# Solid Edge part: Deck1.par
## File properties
Author: Marvin
Template: Iso Metric Part.par
Last saved by: m_hel
Revision: 23
Application: Solid Edge
Accuracy: 0,990
Username: Marvin
Material: Textured White
Face Style: White painted
Fill Style: ANSI36(Marble)
Virtual Style: ANSI36(Marble)
Grouping: Uncategorized
LibraryName: Custom Materials
Coef. of Thermal Exp: 0.0
Thermal Conductivity: 0.0
Specific Heat: 0.0
Modulus of Elasticity: 0.0
Poisson's Ratio: 0.0
Yield Stress: 0.0
Ultimate Stress: 0.0
Elongation: 0.0
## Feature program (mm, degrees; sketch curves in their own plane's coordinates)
sketch for "unnamed Protrusion 1" plane through (0, 0, 0) normal (0, 0, 1) x-axis (1, 0, 0)
  line (-1205, -2870) -> (-1205, -36.0362)
  arc centre (2833.7179, -36.0362) radius 4038.7179 from (-260.1195, 2560.0016) to (-1205, -36.0362) ccw
  line (0, 2870) -> (-260.1195, 2560.0016)
  line (0, -2870) -> (0, 2870)
  line (-1205, -2870) -> (0, -2870)
extrude "unnamed Protrusion 1" add finite 70 along +normal
mirror "unnamed Mirror 1" of "unnamed Protrusion 1" about plane through (0, 0, 0) normal (1, 0, 0)
extrude "unnamed Protrusion 2" add finite 70
sketch for "unnamed Cutout 1" plane through (0, 0, 0) normal (0, 0, 1) x-axis (1, 0, 0)
  line (-805, -1100) -> (805, -1100)
  line (805, -36.0362) -> (805, -1100)
  arc centre (-2833.7179, -36.0362) radius 3638.7179 from (725.5906, 720) to (805, -36.0362) cw
  line (-725.5906, 720) -> (725.5906, 720)
  arc centre (2833.7179, -36.0362) radius 3638.7179 from (-805, -36.0362) to (-725.5906, 720) cw
  line (-805, -1100) -> (-805, -36.0362)
extrude "unnamed Cutout 1" cut through along +normal
sketch for "ExtrudedCutout_2" plane through (0, 0, 70) normal (0, 0, 1) x-axis (0, -1, 0)
  arc centre (36.0362, 2833.7179) radius 3638.7179 from (-1120, -616.4775) to (-1670, -380.2685) cw
  line (-1670, -380.2685) -> (-1670, 380.2685)
  arc centre (36.0362, -2833.7179) radius 3638.7179 from (-1670, 380.2685) to (-1120, 616.4775) cw
  line (-1120, -616.4775) -> (-1120, 616.4775)
extrude "ExtrudedCutout_2" cut finite 50 along -normal
sketch for "ExtrudedCutout_3" plane through (0, 0, 70) normal (0, 0, 1) x-axis (0, -1, 0)
  line (1150, -500) -> (1600, -500)
  line (1600, -500) -> (1600, 500)
  line (1600, 500) -> (1150, 500)
  line (1150, 500) -> (1150, -500)
extrude "ExtrudedCutout_3" cut finite 50 along -normal
sketch for "unnamed Cutout 2" plane through (0, 0, 70) normal (0, 0, 1) x-axis (0, -1, 0)
extrude "unnamed Cutout 2" cut finite 50 along -normal
sketch for "ExtrudedCutout_5" plane through (0, 0, 70) normal (0, 0, 1) x-axis (0, -1, 0)
  line (2150, -250) -> (2150, 250)
  line (2150, 250) -> (1800, 250)
  line (1800, 250) -> (1800, -250)
  line (1800, -250) -> (2150, -250)
extrude "ExtrudedCutout_5" cut finite 50 along -normal
sketch for "unnamed Cutout 3" plane through (0, 0, 70) normal (0, 0, 1) x-axis (0, -1, 0)
  line (953.812, 885) -> (1000, 805)
  line (803.812, 885) -> (953.812, 885)
  line (757.624, 805) -> (803.812, 885)
extrude "unnamed Cutout 3" cut through along -normal
mirror "unnamed Mirror 2" of "unnamed Cutout 3" about plane through (0, 0, 0) normal (1, 0, 0)
extrude "unnamed Cutout 4" cut through
sketch used by "unnamed Cutout 5" plane through (0, 0, 0) normal (0, 0, -1) x-axis (1, 0, 0)
  line (-405.7962, 2870) -> (-300, 2270)
  line (-300, 2270) -> (300, 2270)
  line (300, 2270) -> (405.7962, 2870)
  dimension (linear) = 300
extrude "unnamed Cutout 5" cut through along -normal
sketch for "unnamed Cutout 6" #1 plane through (650, -2250, 20) normal (0, 0, 1) x-axis (0, 1, 0)
  line (430, 430) -> (430, 870)
  arc centre (420, 870) radius 10 from (420, 880) to (430, 870) cw
  line (420, 880) -> (130, 880)
  arc centre (130, 870) radius 10 from (130, 880) to (120, 870) ccw
  line (120, 870) -> (120, 430)
  arc centre (130, 430) radius 10 from (120, 430) to (130, 420) ccw
  line (130, 420) -> (420, 420)
  arc centre (420, 430) radius 10 from (420, 420) to (430, 430) ccw
sketch for "unnamed Cutout 6" #2 plane through (650, -2250, 20) normal (0, 0, 1) x-axis (0, 1, 0)
  line (670, 1120) -> (670, 180)
  arc centre (680, 180) radius 10 from (670, 180) to (680, 170) ccw
  line (680, 170) -> (1070, 170)
  arc centre (1070, 180) radius 10 from (1070, 170) to (1080, 180) ccw
  line (1080, 180) -> (1080, 1120)
  arc centre (1070, 1120) radius 10 from (1080, 1120) to (1070, 1130) ccw
  line (1070, 1130) -> (680, 1130)
  arc centre (680, 1120) radius 10 from (670, 1120) to (680, 1130) cw
sketch for "unnamed Cutout 6" #3 plane through (650, -2250, 20) normal (0, 0, 1) x-axis (0, 1, 0)
  arc centre (2213.9638, 3483.7179) radius 3618.7179 from (3894.6444, 278.9664) to (3403.2866, 66.0241) cw
  arc centre (3400, 75.4686) radius 10 from (3390, 75.4686) to (3403.2866, 66.0241) ccw
  line (3390, 75.4686) -> (3390, 1224.5314)
  arc centre (3400, 1224.5314) radius 10 from (3403.2866, 1233.9759) to (3390, 1224.5314) ccw
  arc centre (2213.9638, -2183.7179) radius 3618.7179 from (3403.2866, 1233.9759) to (3894.6444, 1021.0336) cw
  arc centre (3890, 1012.1775) radius 10 from (3900, 1012.1775) to (3894.6444, 1021.0336) ccw
  line (3900, 1012.1775) -> (3900, 287.8225)
  arc centre (3890, 287.8225) radius 10 from (3894.6444, 278.9664) to (3900, 287.8225) ccw
extrude "unnamed Cutout 6" cut through along -normal
sketch for "unnamed Cutout 7" plane through (650, -2250, 20) normal (0, 0, 1) x-axis (0, 1, 0)
  line (420, 180) -> (-420, 180)
  arc centre (-420, 170) radius 10 from (-420, 180) to (-430, 170) ccw
  line (-430, 170) -> (-430, -170)
  arc centre (-420, -170) radius 10 from (-430, -170) to (-420, -180) ccw
  line (-420, -180) -> (420, -180)
  arc centre (420, -170) radius 10 from (420, -180) to (430, -170) ccw
  line (430, -170) -> (430, 170)
  arc centre (420, 170) radius 10 from (420, 180) to (430, 170) cw
extrude "unnamed Cutout 7" cut through along -normal
mirror "unnamed Mirror 3" of "unnamed Cutout 2", "unnamed Cutout 7" about plane through (0, 0, 0) normal (1, 0, 0)
extrude "unnamed Cutout 8" cut finite 50
extrude "unnamed Cutout 9" cut through
fillet "Round_1" radius 20
fillet "Round_2" radius 10
fillet "Round_3" radius 30
fillet "Round_4" radius 30
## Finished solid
Body 1: solid body, 195 faces, 463 edges, 275 vertices.
  Faces by surface: cylinder 95, plane 64, blend 30, torus 6
  Edges by curve: line 266, circle 126, ellipse 59, intersection 12
Bounding box of the edges (mm; curved faces can reach further): 2410.000 x 5740.000 x 70.000, from (-1205, -2870, 0) to (1205, 2870, 70).
Cylindrical faces by radius (mm): R10 x40, R20 x33, R30 x14, R3618.7179 x2, R3638.7179 x4, R4038.7179 x2
Toroidal faces (ring radius, tube radius in mm): R3658.7179 r20 x4, R4008.7179 r30 x2
Planar faces by outward normal: +x 12, +y 11, +z 6, -x 12, -y 14, -z 1, oblique 8
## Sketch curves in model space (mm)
arc centre (480, -2670, 20) radius 10 from (470, -2670, 20) through (473.1376, -2677.2737, 20) to (480, -2680, 20)
line (480, -2680, 20) -> (820, -2680, 20)
arc centre (820, -2670, 20) radius 10 from (820, -2680, 20) through (827.2737, -2676.8624, 20) to (830, -2670, 20)
line (830, -2670, 20) -> (830, -1830, 20)
arc centre (820, -1830, 20) radius 10 from (830, -1830, 20) through (826.8624, -1822.7263, 20) to (820, -1820, 20)
line (820, -1820, 20) -> (480, -1820, 20)
arc centre (480, -1830, 20) radius 10 from (470, -1830, 20) through (473.1376, -1822.7263, 20) to (480, -1820, 20)
line (470, -1830, 20) -> (470, -2670, 20)
arc centre (-362.1775, 1640, 20) radius 10 from (-362.1775, 1650, 20) through (-367.3523, 1648.557, 20) to (-371.0336, 1644.6444, 20)
line (-362.1775, 1650, 20) -> (362.1775, 1650, 20)
arc centre (362.1775, 1640, 20) radius 10 from (371.0336, 1644.6444, 20) through (367.3523, 1648.557, 20) to (362.1775, 1650, 20)
arc centre (-2833.7179, -36.0362, 20) radius 3618.7179 from (371.0336, 1644.6444, 20) through (486.6064, 1402.9099, 20) to (583.9759, 1153.2866, 20)
arc centre (574.5314, 1150, 20) radius 10 from (574.5314, 1140, 20) through (582.682, 1144.2063, 20) to (583.9759, 1153.2866, 20)
line (574.5314, 1140, 20) -> (-574.5314, 1140, 20)
arc centre (-574.5314, 1150, 20) radius 10 from (-583.9759, 1153.2866, 20) through (-582.682, 1144.2063, 20) to (-574.5314, 1140, 20)
arc centre (2833.7179, -36.0362, 20) radius 3618.7179 from (-583.9759, 1153.2866, 20) through (-486.6064, 1402.9099, 20) to (-371.0336, 1644.6444, 20)
arc centre (-220, -2120, 20) radius 10 from (-230, -2120, 20) through (-226.8624, -2127.2737, 20) to (-220, -2130, 20)
line (-220, -2130, 20) -> (220, -2130, 20)
arc centre (220, -2120, 20) radius 10 from (220, -2130, 20) through (227.2737, -2126.8624, 20) to (230, -2120, 20)
line (230, -2120, 20) -> (230, -1830, 20)
arc centre (220, -1830, 20) radius 10 from (230, -1830, 20) through (226.8624, -1822.7263, 20) to (220, -1820, 20)
line (220, -1820, 20) -> (-220, -1820, 20)
arc centre (-220, -1830, 20) radius 10 from (-230, -1830, 20) through (-226.8624, -1822.7263, 20) to (-220, -1820, 20)
line (-230, -1830, 20) -> (-230, -2120, 20)
arc centre (470, -1570, 20) radius 10 from (470, -1580, 20) through (477.2737, -1576.8624, 20) to (480, -1570, 20)
line (480, -1570, 20) -> (480, -1180, 20)
arc centre (470, -1180, 20) radius 10 from (480, -1180, 20) through (476.8624, -1172.7263, 20) to (470, -1170, 20)
line (470, -1170, 20) -> (-470, -1170, 20)
arc centre (-470, -1180, 20) radius 10 from (-470, -1170, 20) through (-477.2737, -1173.1376, 20) to (-480, -1180, 20)
line (-480, -1180, 20) -> (-480, -1570, 20)
arc centre (-470, -1570, 20) radius 10 from (-470, -1580, 20) through (-477.2737, -1576.8624, 20) to (-480, -1570, 20)
line (-470, -1580, 20) -> (470, -1580, 20)
line (885, -953.812, 70) -> (805, -1000, 70)
line (885, -803.812, 70) -> (885, -953.812, 70)
line (805, -757.624, 70) -> (885, -803.812, 70)
arc centre (-2833.7179, -36.0362, 0) radius 3638.7179 from (725.5906, 720, 0) through (785.0932, 344.0614, 0) to (805, -36.0362, 0)
line (805, -36.0362, 0) -> (805, -1100, 0)
line (-805, -1100, 0) -> (805, -1100, 0)
line (-805, -1100, 0) -> (-805, -36.0362, 0)
arc centre (2833.7179, -36.0362, 0) radius 3638.7179 from (-805, -36.0362, 0) through (-785.0932, 344.0614, 0) to (-725.5906, 720, 0)
line (-725.5906, 720, 0) -> (725.5906, 720, 0)
line (300, -2270, 0) -> (405.7962, -2870, 0)
line (-300, -2270, 0) -> (300, -2270, 0)
line (-405.7962, -2870, 0) -> (-300, -2270, 0)
line (-500, -1600, 70) -> (500, -1600, 70)
line (500, -1600, 70) -> (500, -1150, 70)
line (500, -1150, 70) -> (-500, -1150, 70)
line (-500, -1150, 70) -> (-500, -1600, 70)
line (-250, -2150, 70) -> (250, -2150, 70)
line (250, -2150, 70) -> (250, -1800, 70)
line (250, -1800, 70) -> (-250, -1800, 70)
line (-250, -1800, 70) -> (-250, -2150, 70)
line (450, -2700, 70) -> (850, -2700, 70)
line (850, -2700, 70) -> (850, -1800, 70)
line (850, -1800, 70) -> (450, -1800, 70)
line (450, -1800, 70) -> (450, -2700, 70)
arc centre (-2833.7179, -36.0362, 70) radius 3638.7179 from (380.2685, 1670, 70) through (509.7017, 1399.8654, 70) to (616.4775, 1120, 70)
line (-616.4775, 1120, 70) -> (616.4775, 1120, 70)
arc centre (2833.7179, -36.0362, 70) radius 3638.7179 from (-616.4775, 1120, 70) through (-509.7017, 1399.8654, 70) to (-380.2685, 1670, 70)
line (-380.2685, 1670, 70) -> (380.2685, 1670, 70)
line (0, -2870, 0) -> (0, 2870, 0)
line (0, 2870, 0) -> (-260.1195, 2560.0016, 0)
arc centre (2833.7179, -36.0362, 0) radius 4038.7179 from (-260.1195, 2560.0016, 0) through (-961.4355, 1345.2867, 0) to (-1205, -36.0362, 0)
line (-1205, -2870, 0) -> (-1205, -36.0362, 0)
line (-1205, -2870, 0) -> (0, -2870, 0)
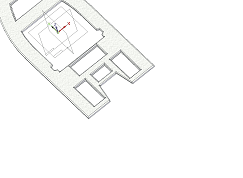
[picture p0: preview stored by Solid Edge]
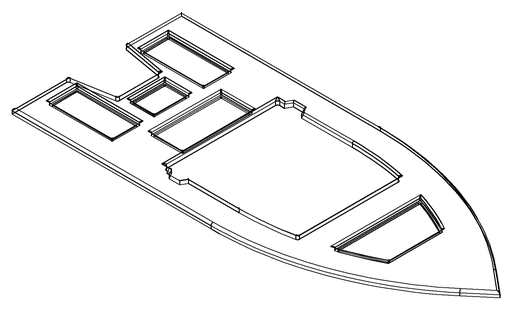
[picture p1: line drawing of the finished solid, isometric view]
